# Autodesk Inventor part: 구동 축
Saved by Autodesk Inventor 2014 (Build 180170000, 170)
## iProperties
Created: 2026-10
Part Number: 구동 축
Material: 일반
Document SubType Name: Modeling
Designer: dg
Density: 1 g/cm^3
Appearance: 기본값
Author: dg
Author: jhkim
Creation Date: 2026-09-29
Sending System: Autodesk Inventor 2027
Preprocessor: ST-DEVELOPER v20.1
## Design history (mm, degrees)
node "구동 축1"
node "솔리드1"
node "기준1"
